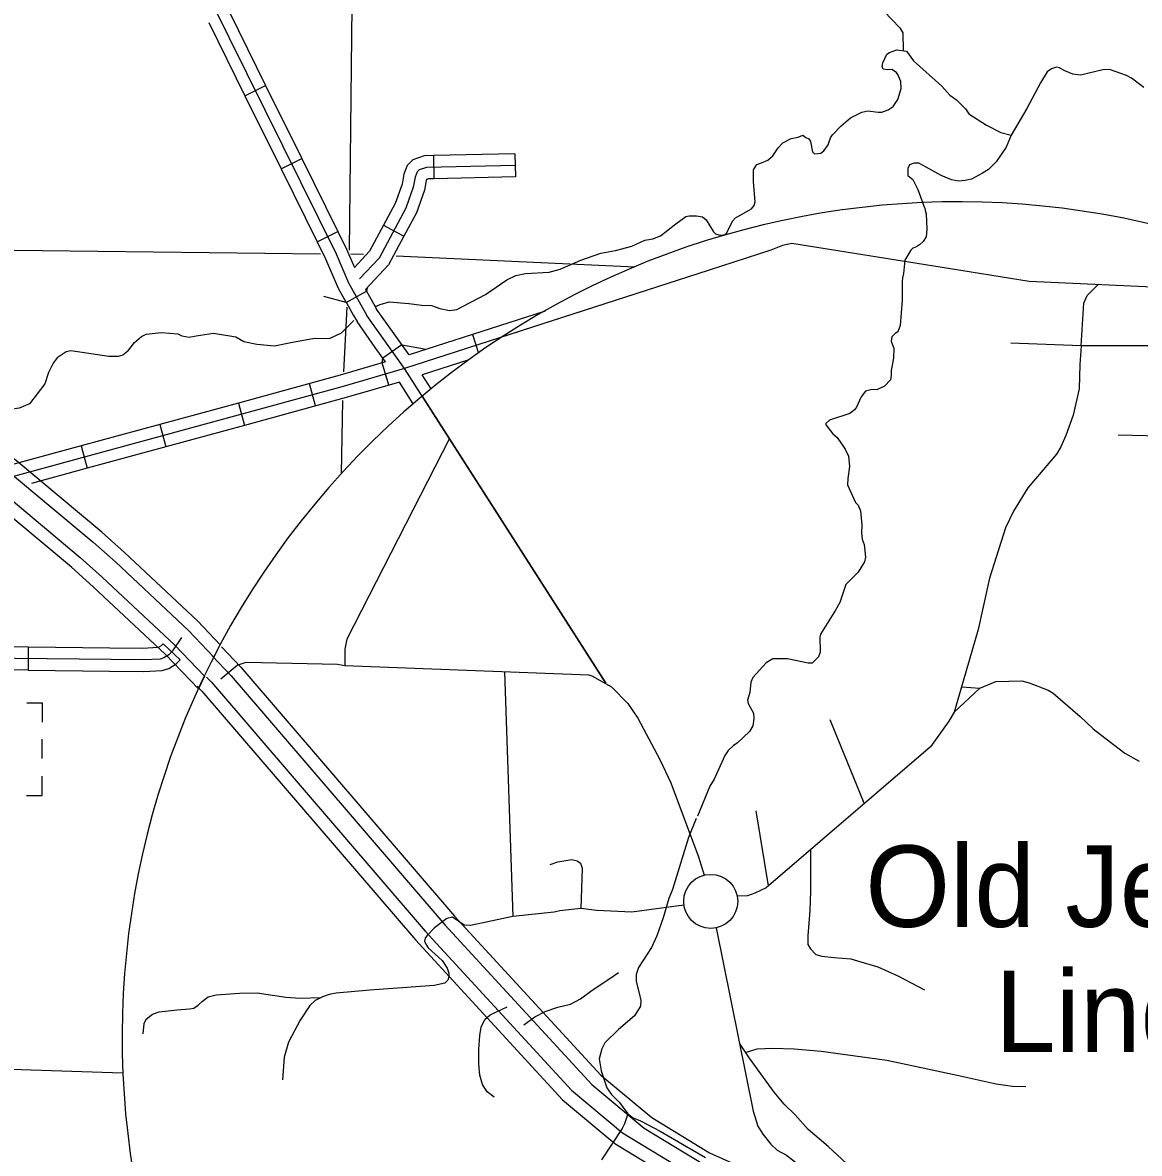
# Model space of a CAD drawing. Extents: x 1370567 to 1373900, y 377514 to 379648.
# Drawn here: x 1372406 to 1372612.6, y 378357.5 to 378566.7 of the extents above; entities that cross this region are included whole.
import ezdxf

# ---------------------------------------------------------------- set-up
doc = ezdxf.new("R2010")
doc.units = 0
doc.layers.add('Default', color=7, linetype='Continuous')

msp = doc.modelspace()

# ---------------------------------------------------------------- linework, layer by layer
at = {"layer": 'Default'}
for p, q in [((1372447.15, 378553.19), (1372450.99, 378555.09)), ((1372482.03, 378542.11), (1372482.13, 378537.82)), ((1372497.12, 378542.45), (1372497.21, 378538.16)), ((1372453.84, 378539.67), (1372457.68, 378541.57)), ((1372460.52, 378526.15), (1372464.36, 378528.05)), ((1372472.81, 378529.22), (1372476.58, 378527.19)), ((1372465.91, 378514.93), (1372469.63, 378517.05)), ((1372489.29, 378509.04), (1372490.4, 378505.59)), ((1372476.19, 378507.12), (1372472.69, 378504.64)), ((1372473.78, 378499.64), (1372472.58, 378503.75)), ((1372460.22, 378495.79), (1372459.09, 378499.93)), ((1372445.96, 378496.34), (1372447.08, 378492.21)), ((1372431.4, 378492.37), (1372432.53, 378488.24)), ((1372416.85, 378488.4), (1372417.98, 378484.27)), ((1372407.09, 378451.18), (1372407.04, 378446.9)), ((1372435.16, 378448.85), (1372432.04, 378451.79)), ((1372409.64, 378430.55), (1372409.65, 378434.12))]:
    msp.add_line(p, q, dxfattribs=at)
for points in [[(1372392.11, 378677.23), (1372410.49, 378630.59), (1372412.3, 378626.75), (1372424.41, 378604.04), (1372464.02, 378523.91), (1372466.31, 378518.55), (1372469.72, 378512.56)], [(1372690.82, 378635.48), (1372686.74, 378602.15), (1372686.34, 378579.4), (1372685.75, 378575.4), (1372685.23, 378572.97), (1372677.85, 378556.98), (1372676.93, 378554.13), (1372676.4, 378537.26), (1372675.45, 378534.52), (1372669.9, 378524.3), (1372668.41, 378522.28), (1372665.43, 378520.17), (1372663.2, 378519.44), (1372652.88, 378517.3), (1372643.76, 378515.3), (1372641.3, 378515.08), (1372637.28, 378516.78), (1372634.77, 378517.08), (1372617.83, 378517.68), (1372592.22, 378518.83), (1372576.17, 378521.4)], [(1372467.52, 378620.72), (1372466.43, 378524.64)], [(1372553.36, 378579.72), (1372553.58, 378579.66), (1372555.13, 378580.08), (1372556.21, 378579.65), (1372556.75, 378579.28), (1372558.15, 378577.93), (1372558.88, 378576.78), (1372561.19, 378573.94), (1372565.45, 378568.78), (1372568.32, 378565.77), (1372568.89, 378564.85), (1372568.96, 378561.57)], [(1372444.31, 378568.62), (1372450.99, 378555.09)], [(1372440.47, 378566.72), (1372447.15, 378553.19)], [(1372567.92, 378557.14), (1372567.69, 378557.51), (1372566.87, 378558.06), (1372566.01, 378557.97), (1372565.24, 378558.12), (1372565.04, 378558.58), (1372565.16, 378559.26), (1372565.93, 378560.89), (1372566.39, 378561.2), (1372567.79, 378561.68), (1372569.53, 378561.42), (1372570.84, 378559.67), (1372576.11, 378554.94), (1372577.59, 378553.3), (1372578.78, 378552.41), (1372580.49, 378550.75), (1372581.11, 378549.86), (1372584.33, 378547.76), (1372586.98, 378546.41), (1372588.92, 378545.89), (1372587.97, 378543.69), (1372586.13, 378540.95), (1372584.7, 378539.55), (1372583.64, 378538.84), (1372581.55, 378537.76), (1372580.38, 378537.48), (1372579.21, 378537.4), (1372577.9, 378537.63), (1372575.98, 378538.41), (1372573.22, 378539.99), (1372571.82, 378540.74), (1372571, 378540.74), (1372570.11, 378540.38), (1372569.79, 378539.72), (1372569.82, 378538.46), (1372570.7, 378537.72), (1372571.66, 378535.85), (1372572.9, 378532.45), (1372573.04, 378532.26)], [(1372530.71, 378530.99), (1372531.83, 378530.79), (1372532.51, 378530.21), (1372533.87, 378527.98), (1372534.21, 378527.66), (1372534.84, 378527.43), (1372535.5, 378527.37), (1372535.95, 378527.52), (1372536.33, 378527.83), (1372537.34, 378529.97), (1372537.91, 378530.62), (1372540.89, 378532.27), (1372541.37, 378532.9), (1372541.55, 378533.59), (1372541.25, 378537.3), (1372541.26, 378539.45), (1372541.89, 378540.47), (1372542.72, 378540.79), (1372543.92, 378541.27), (1372544.84, 378542.04), (1372545.79, 378543.55), (1372546.7, 378544.46), (1372548.22, 378545.26), (1372549.54, 378545.51), (1372550.39, 378545.88), (1372550.91, 378545.48), (1372551.51, 378545.24), (1372551.79, 378544.7), (1372552.18, 378542.81), (1372552.52, 378542.41), (1372553.72, 378542.58), (1372554.24, 378543), (1372555.07, 378544.12), (1372555.5, 378545.4), (1372555.88, 378545.94), (1372557.46, 378547.63), (1372559.18, 378549.13), (1372561.26, 378550.13), (1372562.41, 378550.41), (1372564.29, 378550.12), (1372564.98, 378550.14), (1372566.15, 378550.6), (1372567.1, 378551.22), (1372567.96, 378552.48), (1372568.54, 378554.53), (1372568.51, 378555.85), (1372567.92, 378557.14)], [(1372613.47, 378554.72), (1372611.16, 378556.42), (1372610.28, 378556.96), (1372607.14, 378558.03), (1372605.85, 378558.01), (1372601.74, 378557.02), (1372600.34, 378557.2), (1372598.83, 378557.77), (1372597.83, 378558.38), (1372597.31, 378558.47), (1372596.37, 378558.18), (1372595.6, 378557.61), (1372594.36, 378555.56), (1372591.83, 378550.85), (1372588.92, 378545.89)], [(1372450.99, 378555.09), (1372457.68, 378541.57)], [(1372447.15, 378553.19), (1372453.84, 378539.67)], [(1372482.03, 378542.11), (1372480.35, 378542.07), (1372478.2, 378541.32), (1372477.18, 378540.3), (1372476.58, 378538.69), (1372476.22, 378536.84), (1372474.97, 378533.23), (1372472.81, 378529.22)], [(1372497.12, 378542.45), (1372482.03, 378542.11)], [(1372457.68, 378541.57), (1372464.36, 378528.05)], [(1372497.17, 378540.31), (1372480.74, 378539.93), (1372479.37, 378539.45), (1372479.02, 378539.11), (1372478.65, 378538.11), (1372478.3, 378536.28), (1372476.94, 378532.36), (1372471.97, 378523.16), (1372468.38, 378519.3)], [(1372453.84, 378539.67), (1372460.52, 378526.15)], [(1372482.13, 378537.82), (1372481.13, 378537.8), (1372480.77, 378537.68), (1372480.72, 378537.53), (1372480.37, 378535.73), (1372478.9, 378531.5), (1372476.58, 378527.19)], [(1372497.21, 378538.16), (1372482.13, 378537.82)], [(1372572.92, 378532.22), (1372573.18, 378531.34), (1372573.33, 378528.48)], [(1372471.31, 378514.22), (1372472.15, 378514.58), (1372473.82, 378515.07), (1372477.47, 378514.77), (1372479.89, 378514.44), (1372481.66, 378514.35), (1372483.23, 378513.83), (1372485.03, 378513.48), (1372486.37, 378513.62), (1372491.64, 378516.43), (1372495.59, 378519.16), (1372497.25, 378519.93), (1372499.05, 378520.32), (1372503.42, 378520.57), (1372505.48, 378521.1), (1372509.32, 378522.78), (1372513.03, 378524.08), (1372515.69, 378524.58), (1372518.75, 378525.37), (1372521.16, 378526.45), (1372522.64, 378526.73), (1372524.07, 378527.3), (1372526.85, 378529.52), (1372528.71, 378530.83), (1372529.37, 378530.97), (1372530.71, 378530.99)], [(1372442.61, 378451.61), (1372438.45, 378455.98), (1372424.89, 378468.66), (1372420.69, 378472.43), (1372404.91, 378485.62), (1372343.3, 378528.9)], [(1372464.36, 378528.05), (1372465.97, 378524.8), (1372467.42, 378521.41)], [(1372472.81, 378529.22), (1372470.21, 378524.42), (1372467.42, 378521.41)], [(1372573.33, 378528.48), (1372573.21, 378527.06), (1372572.63, 378526.25), (1372571.97, 378525.6), (1372571.39, 378525.25), (1372570.75, 378524.96), (1372570.33, 378524.6), (1372569.25, 378522.77)], [(1372341.91, 378526.91), (1372403.43, 378483.69), (1372419.1, 378470.59), (1372423.25, 378466.87), (1372436.74, 378454.25), (1372441.42, 378449.33), (1372442.61, 378451.61)], [(1372347.77, 378525.31), (1372461.14, 378523.94)], [(1372460.52, 378526.15), (1372462.07, 378523.01), (1372464.39, 378517.6), (1372465.91, 378514.93)], [(1372476.58, 378527.19), (1372473.73, 378521.9), (1372469.48, 378517.32)], [(1372576.17, 378521.4), (1372548.37, 378525.84), (1372546.6, 378525.51), (1372544.45, 378524.63), (1372533.02, 378520.89)], [(1372576.17, 378521.4), (1372548.37, 378525.84), (1372546.6, 378525.51), (1372544.45, 378524.63), (1372533.02, 378520.89)], [(1372339.77, 378523.87), (1372401.17, 378480.74), (1372416.67, 378467.78), (1372420.74, 378464.13), (1372434.13, 378451.61), (1372439.66, 378445.79)], [(1372466.76, 378523.94), (1372469.12, 378523.85)], [(1372475.12, 378523.6), (1372519.32, 378521.53)], [(1372439.66, 378445.79), (1372438.55, 378443.43), (1372432.42, 378449.89), (1372419.1, 378462.34), (1372415.08, 378465.95), (1372399.69, 378478.81), (1372338.37, 378521.88)], [(1372569.25, 378522.77), (1372568.97, 378520.29), (1372568.79, 378519.5), (1372568.73, 378518.82), (1372568.76, 378515.36), (1372568.4, 378510.67), (1372567.93, 378509.53), (1372567.44, 378509.19)], [(1372623.85, 378517.47), (1372617.83, 378517.68), (1372592.22, 378518.83), (1372576.17, 378521.4)], [(1372533.02, 378520.89), (1372476.67, 378502.71), (1372465.34, 378499.41), (1372402.3, 378482.21), (1372397.56, 378480.59), (1372395.5, 378479.74), (1372393.71, 378478.68), (1372391.79, 378476.83), (1372390.51, 378474.66), (1372389.54, 378472.32), (1372389.11, 378467.95), (1372388.33, 378449.31), (1372387.86, 378403.24)], [(1372533.02, 378520.89), (1372494.81, 378508.57)], [(1372469.48, 378517.32), (1372469.63, 378517.05)], [(1372469.8, 378517.68), (1372469.63, 378517.05)], [(1372469.63, 378517.05), (1372470.99, 378514.65)], [(1372601.89, 378506.92), (1372602.37, 378514.79), (1372603, 378516.22), (1372605.07, 378518.33)], [(1372465.91, 378514.93), (1372461.77, 378516.07)], [(1372465.93, 378514.9), (1372467.27, 378512.54)], [(1372465.47, 378502.08), (1372466.09, 378514.09)], [(1372470.99, 378514.65), (1372471.53, 378513.71)], [(1372474.78, 378509.11), (1372471.53, 378513.71)], [(1372502.69, 378513.36), (1372489.29, 378509.04)], [(1372425.48, 378505.91), (1372426.71, 378507.51), (1372428, 378508.65), (1372428.89, 378509.05), (1372431.69, 378509.38), (1372434.74, 378509.11), (1372435.48, 378508.74), (1372436.83, 378508.53), (1372438.11, 378508.79), (1372441.34, 378509.29), (1372445.45, 378508.56), (1372446.96, 378507.73), (1372449.39, 378507.2), (1372452.61, 378506.91), (1372455.67, 378507.55), (1372460.02, 378508.31), (1372462.78, 378508.26), (1372465.04, 378509.35), (1372467.29, 378511.6)], [(1372467.27, 378512.54), (1372467.91, 378511.41)], [(1372471.28, 378506.64), (1372467.91, 378511.41)], [(1372513.94, 378444.51), (1372476.67, 378502.71), (1372469.72, 378512.56)], [(1372477.52, 378505.24), (1372474.78, 378509.11)], [(1372489.29, 378509.04), (1372477.52, 378505.24)], [(1372567.44, 378509.19), (1372566.84, 378508.6), (1372566.7, 378507.77), (1372566.95, 378507.11)], [(1372473.19, 378503.93), (1372471.28, 378506.64)], [(1372476.19, 378507.12), (1372480.41, 378506.39)], [(1372566.95, 378507.11), (1372567.18, 378506.49), (1372567.17, 378504.65), (1372566.71, 378502.37), (1372566.74, 378501.51), (1372566.57, 378500.6), (1372565.46, 378499.48), (1372564.06, 378498.8), (1372563.2, 378498.86), (1372561.95, 378498.52), (1372561.15, 378497.49), (1372560.29, 378495.55), (1372559.92, 378495.06), (1372559.09, 378494.41), (1372555.32, 378493.18), (1372554.61, 378492.55), (1372554.61, 378492.33), (1372555.95, 378490.61), (1372556.72, 378489.93), (1372558.2, 378487.81), (1372558.8, 378486.53), (1372559, 378484.62), (1372558.69, 378482.36), (1372558.66, 378481.19), (1372560.14, 378477.96), (1372560.63, 378477.42), (1372561.03, 378476.39), (1372561.31, 378473.77), (1372561.25, 378472.31), (1372561.37, 378471.17), (1372561.74, 378470.17), (1372561.94, 378467.83), (1372561.79, 378466.94), (1372560.59, 378465.06), (1372558.34, 378462.78), (1372557.25, 378459.41), (1372556.4, 378458.01), (1372553.65, 378453.59), (1372553.51, 378453.05), (1372553.57, 378450.25), (1372553.28, 378449.39), (1372552.08, 378448.22), (1372551.37, 378448.2), (1372547.54, 378449.03), (1372544.8, 378449), (1372543.6, 378448.29), (1372541.15, 378445.58), (1372540.75, 378444.69), (1372540.6, 378442.81), (1372540.12, 378441.35), (1372540.26, 378440.75), (1372541.23, 378438.93), (1372541.34, 378437.98), (1372541.14, 378436.61), (1372540.49, 378435.59), (1372538.23, 378433.42), (1372537.52, 378432.99), (1372536.55, 378432.05), (1372535.92, 378431.11), (1372534, 378426.77), (1372533.15, 378425.46), (1372530.87, 378419.93)], [(1372601.89, 378506.92), (1372601.63, 378503.48), (1372601.51, 378498.97), (1372600.37, 378494.12), (1372599.06, 378490.35), (1372598.11, 378488.24), (1372597.31, 378486.87), (1372592, 378480.65), (1372589.34, 378476.32), (1372587.89, 378473.23), (1372584.92, 378463.93), (1372582.8, 378454.43), (1372578.37, 378439.13), (1372577.37, 378437.45), (1372573.97, 378432.74), (1372543.62, 378406.67), (1372541.51, 378405.64), (1372540.16, 378405.19), (1372538.24, 378405.13)], [(1372608.73, 378490.43), (1372616.56, 378490.28), (1372617.04, 378490.4), (1372617.38, 378490.97), (1372617.72, 378506.92), (1372601.89, 378506.92), (1372588.87, 378507.4)], [(1372421.96, 378504.96), (1372414.97, 378506), (1372414.06, 378505.78), (1372412.43, 378504.69), (1372411.66, 378503.72), (1372410.83, 378501.98), (1372410.15, 378499.9), (1372407.31, 378496.18), (1372405.38, 378495.38), (1372402.9, 378495.04), (1372400.47, 378494.99), (1372391.99, 378492.9)], [(1372425.48, 378505.91), (1372424.58, 378505.21), (1372423.7, 378504.94), (1372421.96, 378504.96)], [(1372472.53, 378503.74), (1372472.69, 378504.64)], [(1372488.6, 378504.31), (1372479.98, 378501.53)], [(1372473.19, 378503.93), (1372464.76, 378501.47), (1372460.51, 378500.31)], [(1372460.51, 378500.31), (1372445.96, 378496.34)], [(1372475.73, 378500.21), (1372465.92, 378497.35), (1372461.64, 378496.18)], [(1372478.3, 378496.19), (1372475.73, 378500.21)], [(1372481.62, 378498.96), (1372479.98, 378501.53)], [(1372445.96, 378496.34), (1372431.4, 378492.37)], [(1372461.64, 378496.18), (1372447.08, 378492.21)], [(1372465, 378483.3), (1372465.28, 378496.81)], [(1372479.95, 378497.59), (1372513.94, 378444.51)], [(1372431.4, 378492.37), (1372416.85, 378488.4)], [(1372447.08, 378492.21), (1372432.53, 378488.24)], [(1372484.98, 378489.78), (1372466.01, 378452.65), (1372465.64, 378450.8), (1372465.64, 378447.77)], [(1372416.85, 378488.4), (1372403.98, 378484.89)], [(1372432.53, 378488.24), (1372417.98, 378484.27)], [(1372417.98, 378484.27), (1372407.66, 378481.46)], [(1372435.44, 378452.93), (1372433.75, 378450.48), (1372433.07, 378449.76), (1372432.18, 378449.19), (1372431.47, 378448.97), (1372428.33, 378448.8), (1372369.09, 378449.47), (1372328.35, 378450.12), (1372297.62, 378450.9)], [(1372407.09, 378451.18), (1372392.01, 378451.35)], [(1372422.18, 378451.01), (1372407.09, 378451.18)], [(1372432.04, 378451.79), (1372431.69, 378451.43), (1372431.26, 378451.15), (1372431.08, 378451.09), (1372428.28, 378450.94), (1372422.18, 378451.01)], [(1372442.85, 378451.23), (1372446.43, 378447.47), (1372485.96, 378401.42), (1372513.03, 378371.99), (1372522.46, 378364.13), (1372533.11, 378357.64), (1372542.47, 378353.42), (1372553.04, 378349.22), (1372568.33, 378342.77), (1372571.03, 378341.78), (1372620.97, 378321.66)], [(1372422.13, 378446.72), (1372428.37, 378446.65), (1372431.86, 378446.84), (1372433.1, 378447.24), (1372434.44, 378448.1), (1372435.16, 378448.85)], [(1372441.09, 378449.56), (1372444.63, 378445.84), (1372484.15, 378399.81), (1372511.35, 378370.23), (1372521.05, 378362.15), (1372531.98, 378355.49), (1372541.52, 378351.18), (1372552.12, 378346.98), (1372567.44, 378340.51), (1372570.15, 378339.51), (1372619.9, 378319.47)], [(1372442.71, 378445.28), (1372445.74, 378447.84), (1372447.4, 378448.38), (1372464.27, 378448), (1372465.64, 378447.77), (1372510.8, 378446.06), (1372511.37, 378445.88), (1372514.97, 378443.86), (1372517.99, 378440.74), (1372519.85, 378438.06), (1372523.93, 378430.38), (1372525.93, 378426.09), (1372531.06, 378412.39), (1372532.1, 378408.98)], [(1372407.04, 378446.9), (1372391.96, 378447.07)], [(1372407.04, 378446.9), (1372422.13, 378446.72)], [(1372495.21, 378446.58), (1372496.71, 378401.31)], [(1372438.31, 378443.95), (1372439.18, 378443.04), (1372478.7, 378397), (1372505.91, 378367.42), (1372515.6, 378359.34), (1372526.53, 378352.68), (1372536.07, 378348.38), (1372546.68, 378344.17), (1372561.99, 378337.7), (1372564.71, 378336.71), (1372614.45, 378316.66)], [(1372440.07, 378445.62), (1372440.98, 378444.67), (1372480.51, 378398.62), (1372507.59, 378369.18), (1372517.02, 378361.32), (1372527.67, 378354.83), (1372537.02, 378350.62), (1372547.6, 378346.42), (1372562.88, 378339.96), (1372565.58, 378338.97), (1372615.52, 378318.85)], [(1372578.37, 378439.13), (1372583.14, 378443.58), (1372586.08, 378444.8), (1372590.88, 378444.91), (1372592.22, 378444.6), (1372595.79, 378443.23), (1372596.7, 378442.68), (1372601.7, 378438.37), (1372604.06, 378436.08), (1372607.03, 378433.77), (1372609.94, 378431.57), (1372612.6, 378430.08)], [(1372579.77, 378443.84), (1372583.14, 378443.58)], [(1372406.79, 378440.89), (1372409.65, 378440.88), (1372409.65, 378437.31)], [(1372561.72, 378422.33), (1372555.45, 378437.75)], [(1372406.78, 378423.74), (1372409.64, 378423.74), (1372409.64, 378427.31)], [(1372544.01, 378407.01), (1372541.74, 378420.89)], [(1372530.66, 378419.44), (1372529.21, 378415.98), (1372526.26, 378406.31), (1372525.6, 378404.65), (1372524.55, 378401.09), (1372523.35, 378397.78), (1372522.38, 378395.58), (1372519.95, 378391.9), (1372519.52, 378390.59), (1372519.52, 378389.3), (1372520.09, 378387.13), (1372520.4, 378385.79), (1372520.35, 378384.76), (1372519.26, 378382.99), (1372516.26, 378380.45), (1372513.75, 378377.97), (1372513.18, 378376.83), (1372512.72, 378375.01), (1372513.06, 378372.81), (1372514.09, 378369.64), (1372514.95, 378368.41), (1372516.46, 378366.92), (1372518.03, 378364.84), (1372518.97, 378364.07), (1372520.34, 378363.55), (1372523.99, 378361.64), (1372528.87, 378358.78), (1372532.39, 378356.78)], [(1372551.77, 378413.67), (1372551.81, 378406.02), (1372551.69, 378402.47), (1372551.27, 378397.74), (1372551.33, 378396.14), (1372551.81, 378395.37), (1372552.81, 378394.31), (1372553.88, 378394.01), (1372556.18, 378393.78), (1372559.26, 378393.48), (1372561.09, 378392.95), (1372564.22, 378392), (1372567.95, 378390.34), (1372572.86, 378387.8)], [(1372503.65, 378410.95), (1372505.02, 378411.43), (1372507.62, 378411.89), (1372508.65, 378411.66), (1372509.22, 378411.23), (1372509.56, 378410.29), (1372509.3, 378402.81)], [(1372528.39, 378403.46), (1372518.75, 378402.15), (1372512.24, 378402.44), (1372509.3, 378402.81), (1372505.45, 378402.36), (1372504.39, 378402.13), (1372496.71, 378401.31), (1372488.89, 378399.69), (1372487.75, 378399.71), (1372485.58, 378401.2), (1372484.52, 378400.94), (1372482.24, 378399.23)], [(1372482.24, 378399.23), (1372480.8, 378397.74), (1372480.52, 378397.31), (1372480.4, 378396.79), (1372480.6, 378396.2), (1372481.03, 378395.53), (1372483.64, 378393.2), (1372484.58, 378391.78), (1372484.9, 378390.84), (1372484.9, 378390.17), (1372484.7, 378389.54), (1372484.15, 378388.98), (1372482.14, 378388.59), (1372479.66, 378388.39), (1372470.29, 378387.74), (1372464.03, 378387.15), (1372462.73, 378386.91), (1372461.54, 378386.5), (1372460.18, 378385.79), (1372459.18, 378384.9), (1372457.4, 378382.18), (1372455.22, 378378.1), (1372454.39, 378375.32), (1372454.09, 378371.12)], [(1372534.33, 378399.23), (1372541.18, 378365.31), (1372542.04, 378362.54), (1372542.98, 378361.05), (1372544.46, 378359.2), (1372545.63, 378358.08), (1372547.34, 378357.17), (1372549.57, 378355.48), (1372550.63, 378354.2), (1372551, 378353), (1372549.77, 378346.72)], [(1372498.77, 378381.27), (1372500.82, 378382.77), (1372502.71, 378383.78), (1372505.07, 378384.55), (1372507.38, 378385.14), (1372509.27, 378386.08), (1372511.4, 378387.74), (1372514.47, 378389.75), (1372516.25, 378390.99)], [(1372428.31, 378379.64), (1372428.49, 378381.53), (1372428.9, 378382.36), (1372430.09, 378383.24), (1372431.27, 378383.72), (1372434.64, 378384.07), (1372436.89, 378384.25), (1372437.71, 378384.37), (1372438.48, 378384.96), (1372439.31, 378385.67), (1372440.37, 378386.5), (1372441.85, 378386.85), (1372446.17, 378387.15), (1372449.42, 378387.21), (1372454.74, 378386.44), (1372457.4, 378386.2), (1372461.24, 378386.34)], [(1372493.25, 378367.92), (1372491.95, 378368.93), (1372491.12, 378370.23), (1372490.65, 378372), (1372490.41, 378374.07), (1372490.41, 378376.74), (1372490.65, 378379.34), (1372490.88, 378380.88), (1372491.53, 378382.3), (1372492.54, 378383.13), (1372495.69, 378384.61)], [(1372565.31, 378342.72), (1372564.66, 378347.11), (1372561.79, 378352.56), (1372555.08, 378358.76), (1372551.37, 378361.93), (1372548.95, 378364.62), (1372546.92, 378366.62), (1372545.09, 378368.84), (1372542.61, 378372.22), (1372540.5, 378375.13), (1372538.64, 378377.91)], [(1372539.78, 378376.2), (1372541.95, 378376.88), (1372544.79, 378376.97), (1372548.78, 378376.88), (1372553.75, 378376.44), (1372565.9, 378374.75), (1372578.94, 378372), (1372586.12, 378370.41), (1372589.14, 378369.96), (1372591.64, 378369.86)], [(1372370.04, 378374.18), (1372424.53, 378372.4)], [(1372518.03, 378364.84), (1372517.4, 378362.98), (1372516.94, 378362.1), (1372513.14, 378356.31)]]:
    msp.add_lwpolyline(points, dxfattribs=at)
msp.add_circle((1372533.34, 378404.14), 5, dxfattribs=at)
msp.add_arc((1372579.09, 378378.92), 154.64, 48.844, 228.844, dxfattribs=at)

# ---------------------------------------------------------------- texts
for s, p in [('Old Jenny', (1372561.93, 378399.41)), ('Lind', (1372585.94, 378376.24))]:
    msp.add_text(s, height=15.086, dxfattribs=at).set_placement(p)

doc.saveas('drawing.dxf')
